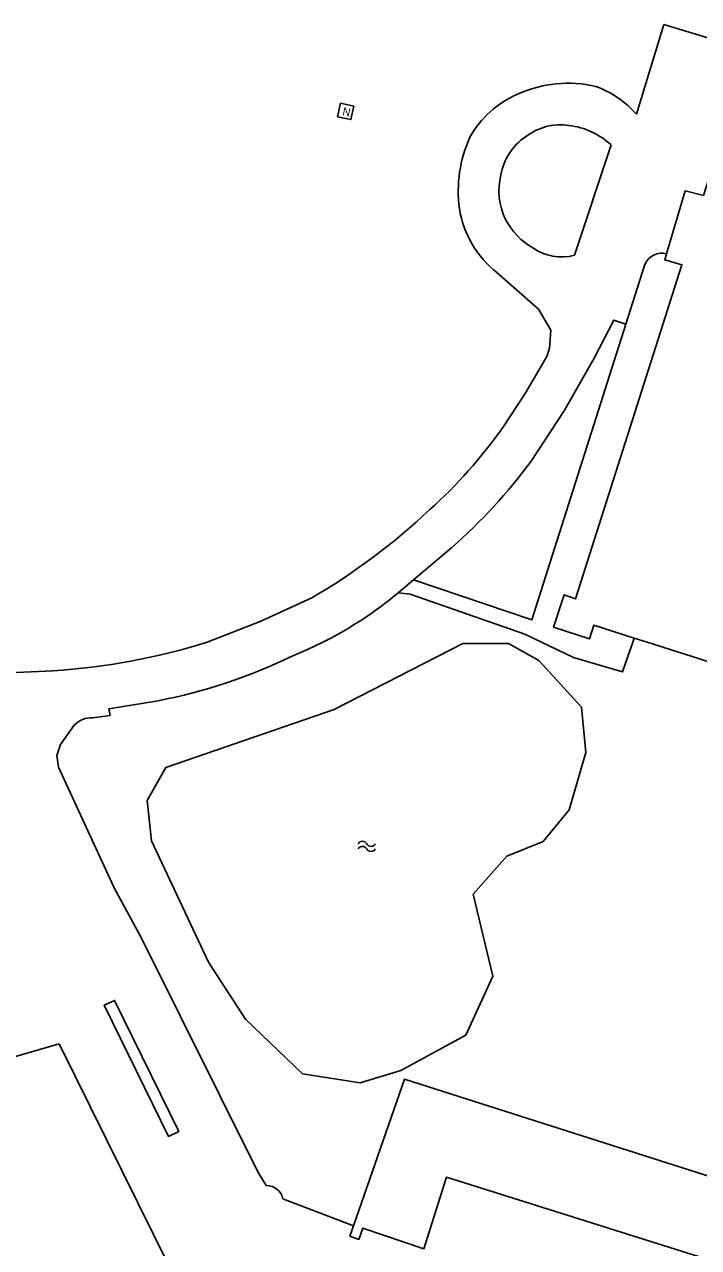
# Model space of a CAD drawing. Extents: x 135990 to 139000, y 393500 to 396000.
# Drawn here: x 137101.8 to 137160.7, y 394947 to 395054.1 of the extents above; entities that cross this region are included whole.
import ezdxf

# ---------------------------------------------------------------- set-up
doc = ezdxf.new("R2010")
doc.units = 0
for name, color, linetype in [('gg-bbg-hoofdgebouw', 7, 'Continuous'), ('gg-knt-verharding', 7, 'Continuous'), ('gg-kntw-bovenkant insteek waterloop', 7, 'Continuous'), ('gt-grn-vlakafsluiter', 7, 'Continuous'), ('gt-symb-nortonput', 7, 'Continuous'), ('gt-symb-watersymbool', 7, 'Continuous')]:
    doc.layers.add(name, color=color, linetype=linetype)

# ---------------------------------------------------------------- blocks, each defined once
blk = doc.blocks.new('gt0-WA')
at = {"layer": 'gt-symb-watersymbool'}
for centre, start, end in [((-0.32, 0.02), 28.0725, 151.9275), ((0.43, 0.42), 208.0725, 331.9275), ((-0.32, -0.43), 28.0725, 151.9275), ((0.43, -0.03), 208.0725, 331.9275)]:
    blk.add_arc(centre, 0.425, start, end, dxfattribs=at)
blk = doc.blocks.new('gt0-NPUT')
at = {"layer": 'gt-symb-nortonput'}
blk.add_lwpolyline([(-0.57, -0.61), (-0.57, 0.59), (0.63, 0.59), (0.63, -0.61)], close=True, dxfattribs=at)
blk.add_text('N', height=0.7, dxfattribs=at).set_placement((-0.22, -0.38))

msp = doc.modelspace()

# ---------------------------------------------------------------- linework, layer by layer
at = {"layer": 'gg-bbg-hoofdgebouw'}
msp.add_line((137155.124, 395000.363), (137156.261, 395000), dxfattribs=at)
for points in [[(137157.956, 395033.981), (137159.58, 395039.492), (137161.18, 395039.072), (137165.225, 395051.755)], [(137157.956, 395033.981), (137157.8, 395033.452), (137159.3, 395033.032), (137149.98, 395003.792), (137149.01, 395004.15), (137148.08, 395001.311), (137151.21, 395000.291), (137151.59, 395001.492), (137155.124, 395000.363)], [(137156.261, 395000), (137176.74, 394993.46), (137167.47, 394964.4), (137170.52, 394963.428), (137166.76, 394951.648), (137135.04, 394961.768), (137130.583, 394948.941)], [(137130.583, 394948.941), (137130.27, 394948.04), (137131.06, 394947.759), (137131.41, 394948.751), (137136.74, 394946.939), (137138.71, 394953.189), (137187.111, 394937.944)]]:
    msp.add_lwpolyline(points, dxfattribs=at)
at = {"layer": 'gg-knt-verharding'}
for p, q in [((137157.71, 395054.05), (137155.31, 395046.19)), ((137149.9, 395033.86), (137153.1, 395043.51)), ((137154.391, 395027.839), (137156.05, 395033.06)), ((137139.19, 395008.29), (137135.831, 395005.458)), ((137135.831, 395005.458), (137134.475, 395004.315)), ((137134.03, 395003.94), (137134.475, 395004.315)), ((137154.999, 395000), (137155.124, 395000.363)), ((137130.583, 394948.941), (137124.41, 394951.29))]:
    msp.add_line(p, q, dxfattribs=at)
for points in [[(137143.1, 395032.35), (137146.76, 395029.14), (137147.82, 395027.29), (137147.72, 395025.73), (137147.47, 395024.99), (137145.58, 395021.76), (137143.63, 395018.78)], [(137154.391, 395027.839), (137146.17, 395001.97), (137135.831, 395005.458)], [(137154.391, 395027.839), (137153.34, 395028.18), (137151.62, 395024.84), (137149.01, 395020.25), (137146.11, 395015.85)], [(137134.475, 395004.315), (137135.54, 395004.22), (137145.55, 395000.7), (137147.015, 395000)], [(137126.93, 395003.88), (137122.41, 395001.81), (137117.78, 395000)], [(137125.22, 394998.78), (137126.574, 394999.362), (137127.902, 395000)], [(137147.015, 395000), (137149.82, 394998.66), (137154.11, 394997.4), (137154.999, 395000)], [(137089.962, 394998.789), (137093.24, 394997.81), (137097.3, 394997.19), (137104.3, 394997.5)], [(137107.78, 394993.4), (137109.3, 394993.59), (137109.2, 394994.18), (137113.51, 394994.88)], [(137122.96, 394952.48), (137122.25, 394953.62), (137112.05, 394974.1), (137109.66, 394978.5), (137104.79, 394989.07), (137104.66, 394990.09), (137104.97, 394991.04), (137106.17, 394992.74)], [(137115.31, 394957.19), (137114.41, 394956.758), (137108.79, 394968.24), (137109.69, 394968.67), (137115.31, 394957.19)], [(137104.84, 394964.853), (137114.46, 394945.42), (137115.17, 394943.61), (137115.63, 394941.73), (137115.8, 394941.74), (137115.69, 394940.58), (137115.42, 394939.26), (137104.51, 394905.86)]]:
    msp.add_lwpolyline(points, dxfattribs=at)
for centre, radius, start, end in [((137148.367, 395039.958), 8.7, 113.26654, 150.96546), ((137149.32, 395038.383), 10.526, 76.54015, 114.64877), ((137149.029, 395040.833), 8.256, 40.45959, 70.60583), ((137148.688, 395040.311), 4.963, 81.52063, 128.0409), ((137148.596, 395038.633), 6.639, 47.28118, 82.87269), ((137151.176, 395039.454), 11.438, 155.59587, 187.65652), ((137148.442, 395040.028), 5.048, 123.85425, 170.0495), ((137148.869, 395039.496), 5.579, 165.42397, 206.57875), ((137148.722, 395039.377), 8.999, 189.25245, 231.33701), ((137149.047, 395039.577), 5.774, 206.50577, 241.13671), ((137148.759, 395037.933), 4.23, 233.79312, 285.6526), ((137157.534, 395032.421), 1.616, 74.867, 156.71368), ((137108.512, 395043.561), 42.981, 311.96096, 324.79178), ((137106.736, 395044.943), 48.956, 311.52236, 323.53917), ((137097.994, 395053.319), 57.285, 300.33984, 313.25769), ((137111.938, 395031.565), 35.372, 296.82812, 308.64989), ((137100.519, 395055.477), 58.1, 273.73092, 287.28248), ((137104.411, 395041.731), 47.726, 280.99091, 295.84963), ((137107.713, 394991.27), 2.131, 88.19346, 136.38771), ((137122.937, 394950.974), 1.507, 12.12492, 89.12434)]:
    msp.add_arc(centre, radius, start, end, dxfattribs=at)
at = {"layer": 'gg-kntw-bovenkant insteek waterloop'}
msp.add_lwpolyline([(137149.43, 394985.34), (137147.16, 394982.56), (137143.99, 394981.27), (137141.03, 394977.95), (137142.76, 394970.77), (137140.39, 394965.63), (137134.73, 394962.54), (137131.17, 394961.44), (137126.11, 394962.25), (137121.13, 394967.03), (137117.91, 394972.02), (137112.93, 394982.63), (137112.53, 394986.16), (137114.17, 394989.03), (137128.9, 394994.12), (137140.13, 394999.9), (137144.13, 394999.9), (137146.78, 394998.39), (137150.51, 394994.33), (137150.9, 394990.34), (137149.43, 394985.34)], dxfattribs=at)
at = {"layer": 'gt-grn-vlakafsluiter'}
msp.add_line((137157.71, 395054.05), (137165.225, 395051.755), dxfattribs=at)
msp.add_lwpolyline([(137100.586, 394976.854), (137088.067, 394971.386), (137092.479, 394961.283), (137104.84, 394964.853)], dxfattribs=at)

# ---------------------------------------------------------------- block references
at = {"layer": 'gt-symb-nortonput', "rotation": -12.062746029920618}
msp.add_blockref('gt0-NPUT', (137129.868, 395046.458), dxfattribs=at)
at = {"layer": 'gt-symb-watersymbool'}
msp.add_blockref('gt0-WA', (137131.685, 394982.146), dxfattribs=at)

doc.saveas('drawing.dxf')
